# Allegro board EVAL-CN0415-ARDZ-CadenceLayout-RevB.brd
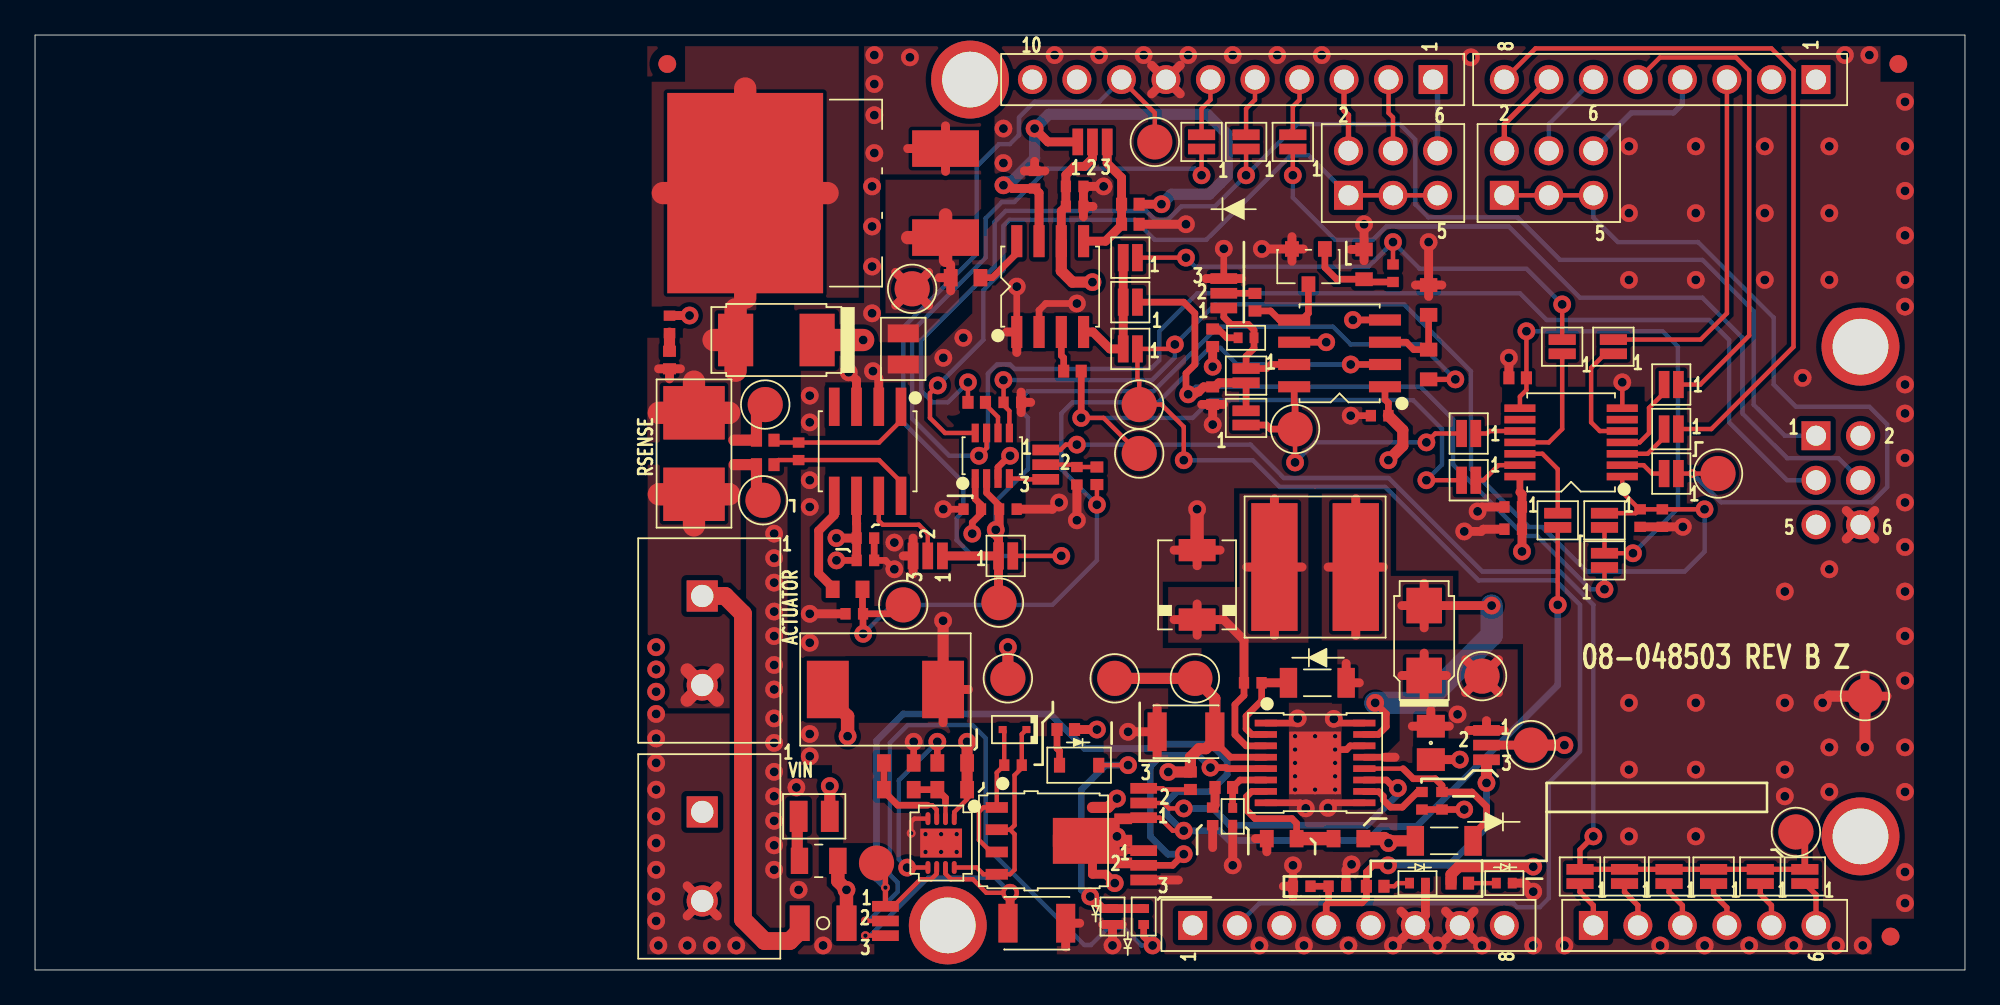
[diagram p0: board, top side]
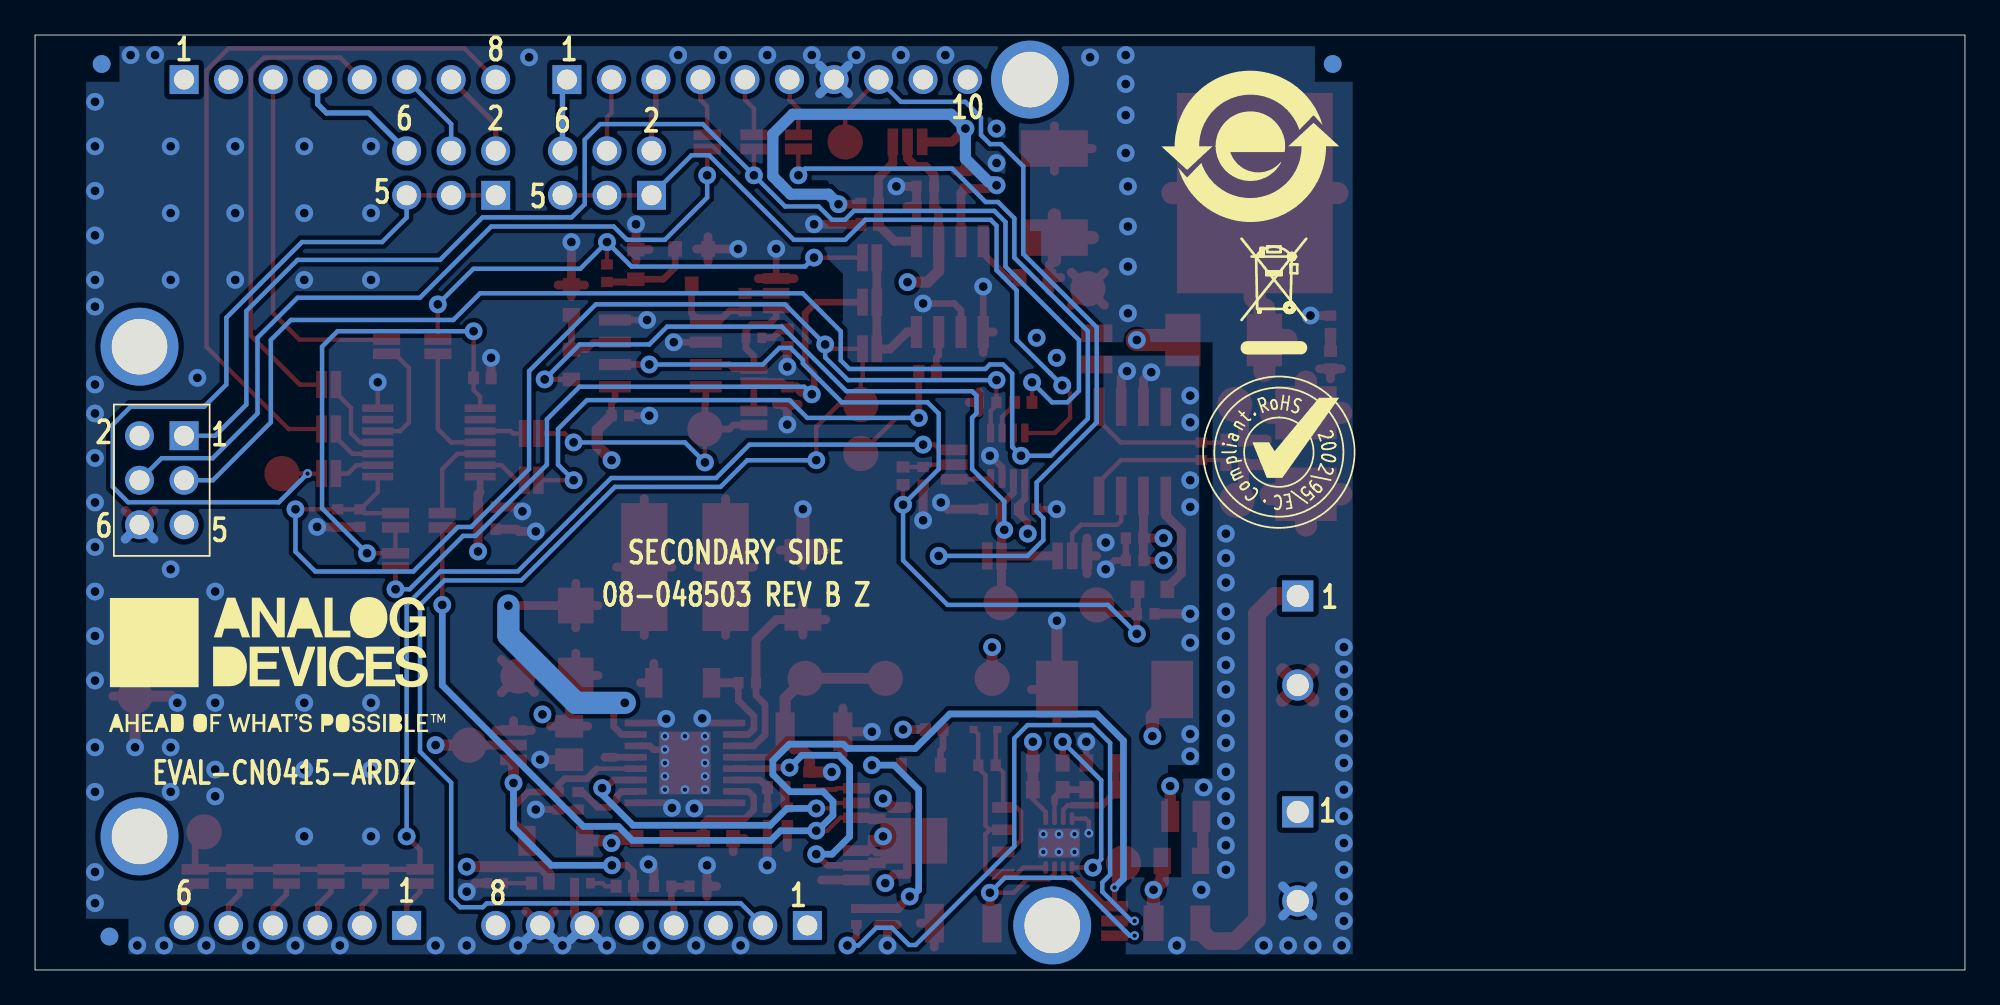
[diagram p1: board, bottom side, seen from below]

Outline 110.1 x 53.34 mm; copper layers: TOP, L2_GND, L3_PWR, BOTTOM. Coordinates in mm from the lower left corner of the outline.
Outline path: 0,53.34 0,0 110.1,0 110.1,53.34 0,53.34

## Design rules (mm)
constraint set DEFAULT: min track width 0.305

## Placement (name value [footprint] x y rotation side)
C1  0.0082uF  [C0402]  43.56 29.59 90 top
C2  4.7uF  [C0402]  59.44 28.19 270 top
C3  10uF  [C0402]  57.02 45.08 90 top
C4  4.7uF  [C0402]  53.47 26.29 180 top
C5  0.1UF  [C0402]  59.31 43.56 0 top
C6  4.7uF  [C0402]  55.75 32.38 0 top
C7  4.7uF  [C0402]  55.5 26.29 0 top
C8  4.7uF  [C0402]  84.33 26.42 180 top
C9  0.1UF  [C0402]  84.33 25.15 0 top
C10  1000pF  [C0402]  55.79 11.68 0 top
C11  0.1UF  [C0402]  47.37 23.37 0 top
C12  4.7uF  [C1210H87]  57.15 2.67 0 top
C14  2.2uF  [C1210H87]  65.66 13.59 180 top
C15  330PF  [C0402H22]  68.33 8.76 270 top
C16  0.1UF  [C0402]  69.47 16.38 180 top
C17  1000pF  [C0402]  67.18 8.76 270 top
C18  0.01UF  [C0402]  79.12 9.65 270 top
C19  0.1UF  [C0402]  80.26 9.65 270 top
C20  0.1UF  [C0402]  74.3 4.78 0 top
C21  10uF  [C0402]  72.26 4.78 180 top
C22  22UF  [C0805H60]  79.63 12.95 270 top
C23  0.1UF  [C0402]  76.71 31.62 180 top
C24  1000pF  [C0402]  36.2 36.83 90 top
C25  0.1UF  [C0402]  77.47 39.75 90 top
C26  4.7uF  [C0402]  59.31 44.7 0 top
C27  4.7uF  [C0402]  91.57 25.78 270 top
C28  0.1UF  [C0402]  92.84 25.78 90 top
C29  4.7uF  [C0402]  47.37 24.64 0 top
C30  4.7uF  [C0402]  46.74 20.32 180 top
D1  SMC3K60CAHM3/9A  [DO214AB_A]  48.51 16 0 top
D2  ACGRBT303-HF  [D2114]  42.29 35.94 180 top
D3  1SS355VMTE-17  [SOD323-4]  59.56 11.68 180 top
D4  BZX585-C15  [SOD523]  55.88 13.72 180 top
D5  B160B-13-F  [DIO214AA]  66.29 21.97 90 top
D6  FDLL914B  [SOD80C]  73.15 16.38 0 top
D7  B220A-13-F  [SMA]  79.25 18.8 90 top
D8  FDLL914B  [SOD80C]  80.39 7.37 180 top
DS1  SML-P11MTT86  [LED0402]  61.47 3.05 90 top
DS2  SML-P11VTT86  [LED0402]  63.25 3.05 90 top
DS3  SML-P11MTT86  [LED0402]  78.87 4.95 180 top
DS4  SML-P11MTT86  [LED0402]  83.82 4.95 180 top
DS5  SML-P11VTT86  [LED0402]  69.09 36.07 0 top
E1  180OHM AT 100MEGHZ  [L0805H35]  49.53 35.43 270 top
E2  180OHM AT 100MEGHZ  [L0805H35]  44.45 8.76 0 top
F1  3A  [F1206]  44.96 2.67 0 top
F2  0.5A  [F0805]  44.7 6.22 180 top
JP1  3PIN_SOLDER_JUMPER  [JPRSLD03]  50.93 23.62 180 top
JP2  3PIN_SOLDER_JUMPER  [JPRSLD03]  57.66 28.83 270 top
JP3  3PIN_SOLDER_JUMPER  [JPRSLD03]  82.8 12.83 270 top
JP4  3PIN_SOLDER_JUMPER  [JPRSLD03]  60.33 47.24 0 top
JP5  3PIN_SOLDER_JUMPER  [JPRSLD03]  63.25 5.97 270 top
JP6  3PIN_SOLDER_JUMPER  [JPRSLD03]  48.51 2.79 270 top
JP7  3PIN_SOLDER_JUMPER  [JPRSLD03]  63.25 9.52 90 top
JP8  3PIN_SOLDER_JUMPER  [JPRSLD03]  67.82 38.61 90 top
L1  100UH  [LSMSQ264H118_A]  73.03 22.99 180 top
NOREF  -  []  -45.72 -66.04 0 top
NOREF#2  -  []  135.89 92.84 0 top
NOREF#3  -  []  107.95 0.13 90 top
NOREF#4  -  [unnamed#2]  53.34 50.8 0 top
NOREF#5  -  []  -45.72 -66.04 0 top
NOREF#6  -  [unnamed#2]  52.07 2.54 0 top
NOREF#7  -  []  107.95 53.47 180 top
NOREF#8  -  []  34.16 53.47 0 top
NOREF#9  -  []  -45.72 -66.04 0 top
NOREF#10  -  []  34.16 0.13 0 top
NOREF#11  -  []  10.48 322.05 0 top
NOREF#12  -  []  70.87 62.36 0 top
NOREF#13  -  [unnamed#2]  104.14 7.62 0 top
NOREF#14  -  [unnamed#2]  106.3 51.69 0 top
NOREF#15  -  []  34.16 53.47 0 top
NOREF#16  -  [unnamed#2]  36.07 51.69 0 top
NOREF#17  -  [unnamed#2]  104.14 35.56 0 top
NOREF#18  -  []  107.95 0.13 90 top
NOREF#19  -  []  34.24 18.41 0 top
NOREF#20  -  []  34.16 7.13 0 top
NOREF#21  -  []  52.07 2.54 0 top
NOREF#22  -  []  34.16 0.13 0 top
NOREF#23  -  []  34.16 53.47 270 top
NOREF#24  -  []  107.95 0.13 0 top
NOREF#25  -  []  34.16 0.13 0 top
NOREF#26  -  []  52.07 2.54 0 top
NOREF#27  -  []  130.81 30.48 0 top
NOREF#28  -  [unnamed#2]  105.85 1.9 0 top
NOREF#29  -  []  -1.91 238.76 0 top
NOREF#30  -  []  39.14 29.54 180 bottom
NOREF#31  -  [unnamed#2]  36.07 51.69 180 bottom
NOREF#32  -  [unnamed#2]  105.85 1.9 180 bottom
NOREF#33  -  []  39.62 35.18 180 bottom
NOREF#34  -  []  40.77 46.99 180 bottom
NOREF#35  -  [unnamed#2]  106.3 51.69 180 bottom
NOREF#36  -  []  96.27 17.4 180 bottom
P1  OSTTC022162  [CNHDR1X2H406]  38.06 9.02 270 top
P2  TSW-103-08-G-D  [CNSAMTEC2X3H330LD36]  74.93 44.2 0 top
P3  SSQ-103-03-T-D  [CNSAMTECSSQ-103-XX-X-D]  101.6 30.48 270 bottom
P4  SSQ-106-03-T-S  [CNSAMTECSSQ-106-XX-X-S]  88.9 2.54 0 top
P5  SSQ-108-03-T-S  [CNSAMTECSSQ-108-XX-X-S]  66.04 2.54 0 top
P6  SSQ-110-03-T-S  [CNSAMTECSSQ-110-XX-X-S]  79.76 50.8 180 top
P7  SSQ-108-03-T-S  [CNSAMTECSSQ-108-XX-X-S]  101.6 50.8 180 top
P8  OSTTC022162  [CNHDR1X2H406]  38.06 21.34 270 top
P9  -  [JPSLD02]  55.37 23.62 0 top
P10  -  [JPSLD02]  88.14 5.33 90 top
P11  -  [JPSLD02]  90.68 5.33 90 top
P12  -  [JPSLD02]  93.22 5.33 90 top
P13  -  [JPSLD02]  95.76 5.33 90 top
P14  -  [JPSLD02]  98.43 5.33 90 top
P15  -  [JPSLD02]  100.97 5.33 90 top
P16  -  [JPSLD02]  71.75 47.24 90 top
P17  -  [JPSLD02]  69.09 47.24 90 top
P18  -  [JPSLD02]  66.55 47.24 90 top
P19  -  [JPSLD02]  81.79 27.94 180 top
P20  -  [JPSLD02]  86.87 25.65 270 top
P21  -  [JPSLD02]  69.09 33.91 270 top
P22  -  [JPSLD02]  69.09 31.5 90 top
P23  -  [JPSLD02]  87.12 35.56 90 top
P24  -  [JPSLD02]  81.79 30.61 180 top
P25  -  [JPSLD02]  93.34 28.32 180 top
P26  -  [JPSLD02]  62.48 35.43 180 top
P27  -  [JPSLD02]  62.48 40.64 180 top
P28  -  [JPSLD02]  62.48 38.1 180 top
P29  -  [JPSLD02]  93.34 30.86 180 top
P30  -  [JPSLD02]  93.34 33.4 180 top
P31  -  [JPSLD02]  90.04 35.56 270 top
P32  -  [JPSLD02]  89.53 23.37 90 top
P34  TSW-103-08-G-D  [CNSAMTEC2X3H330LD36]  83.82 44.2 0 top
P36  -  [JPSLD02]  89.53 25.65 270 top
Q1  CSD19535KTTT  [D2PAK]  44.96 44.32 90 top
Q2  SI7942DP-T1-E3  [POWERPAKSO8_DUAL]  57.53 7.37 270 top
Q3  2N7002LT1G  [SOT23-M3]  72.64 40.13 180 top
R1  0.1  [R2512-2]  37.59 29.46 90 top
R2  10  [R0402]  41.66 28.83 0 top
R3  10  [R0402]  41.66 30.23 0 top
R4  2.2  [R0603]  53.09 39.5 0 top
R5  51  [R0402]  60.58 28.19 90 top
R6  1K  [R0402]  84.58 33.78 180 top
R7  10  [R0402]  59.18 34.16 0 top
R8  10K  [R0603]  79.5 38.23 90 top
R9  2K  [R0603]  79.5 34.54 270 top
R10  84.5K  [R0402]  62.48 42.54 0 top
R11  330K  [R0402]  62.48 43.69 0 top
R12  33  [R0402]  53.72 32.38 180 top
R13  5.1K  [R0402]  58.8 13.72 180 top
R14  1MEG  [R0603]  52.32 10.29 180 top
R15  280K  [R0603]  49.28 10.29 180 top
R16  27K  [R0603]  49.28 11.81 0 top
R17  510K  [R0603]  52.32 11.81 0 top
R18  5.1K  [R0402]  76.45 4.78 0 top
R19  68K  [R0402]  67.82 10.41 180 top
R20  97.6K  [R0603]  71.12 7.49 180 top
R21  300K  [R0603]  74.93 7.49 0 top
R22  100K  [R0402]  65.91 10.79 90 top
R23  5.1K  [R0402]  81.28 4.95 0 top
R24  10K  [R0603]  75.82 40.26 90 top
R25  1K  [R0402]  67.18 32.77 270 top
R26  5.1K  [R0402]  67.18 36.07 90 top
R27  4.99K  [R0402]  69.6 38.1 270 top
R28  100  [R0402]  36.2 34.8 90 top
R29  0  [R0603]  46.36 21.72 0 top
SECONDARY SIDE  -  []  129.16 39.5 270 top
TP1  SMOX/060/B1/R2K GOLD  [CNOXLEYSMOX_060_B1]  49.53 20.83 0 top
TP2  SMOX/060/B1/R2K GOLD  [CNOXLEYSMOX_060_B1]  50.04 38.86 270 top
TP3  SMOX/060/B1/R2K GOLD  [CNOXLEYSMOX_060_B1]  62.99 29.46 180 top
TP4  SMOX/060/B1/R2K GOLD  [CNOXLEYSMOX_060_B1]  41.53 26.8 0 top
TP5  SMOX/060/B1/R2K GOLD  [CNOXLEYSMOX_060_B1]  41.66 32.26 0 top
TP6  SMOX/060/B1/R2K GOLD  [CNOXLEYSMOX_060_B1]  54.99 20.95 90 top
TP7  SMOX/060/B1/R2K GOLD  [CNOXLEYSMOX_060_B1]  61.59 16.64 90 top
TP8  SMOX/060/B1/R2K GOLD  [CNOXLEYSMOX_060_B1]  85.34 12.83 90 top
TP9  SMOX/060/B1/R2K GOLD  [CNOXLEYSMOX_060_B1]  82.55 16.76 0 top
TP10  SMOX/060/B1/R2K GOLD  [CNOXLEYSMOX_060_B1]  55.5 16.64 90 top
TP11  SMOX/060/B1/R2K GOLD  [CNOXLEYSMOX_060_B1]  104.39 15.62 180 top
TP12  SMOX/060/B1/R2K GOLD  [CNOXLEYSMOX_060_B1]  62.99 32.26 180 top
TP13  SMOX/060/B1/R2K GOLD  [CNOXLEYSMOX_060_B1]  66.17 16.64 180 top
TP14  SMOX/060/B1/R2K GOLD  [CNOXLEYSMOX_060_B1]  100.46 7.87 0 top
TP15  SMOX/060/B1/R2K GOLD  [CNOXLEYSMOX_060_B1]  96.01 28.32 270 top
TP16  SMOX/060/B1/R2K GOLD  [CNOXLEYSMOX_060_B1]  63.88 47.24 90 top
TP17  SMOX/060/B1/R2K GOLD  [CNOXLEYSMOX_060_B1]  71.88 30.86 0 top
TP18  SMOX/060/B1/R2K GOLD  [CNOXLEYSMOX_060_B1]  48.01 6.1 180 top
U1  AD8210WYRZ  [SO8]  47.5 29.59 180 top
U2  LTC4441ES8-1#PBF  [SO8NB-5]  57.91 38.99 0 top
U3  LTC2312HTS8-14#TRMPBF  [TSOT-8]  54.61 29.34 0 top
U4  ADG3304BRUZ  [TSSOP14]  87.63 30.1 90 top
U5  LTC4367CDD-1#PBF  [DFN8_3X3_PAD2_38X1_65]  51.69 7.24 180 top
U6  LT3433IFE#TRPBF  [TSSOP16_PAD3_58X2_94]  73.03 11.81 270 top
U7  LT1671IS8#PBF  [SO8NB-5]  74.42 35.18 90 top

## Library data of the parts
C1 = CAP: User Part Number: UPN; Tolerance: 10; alternate symbols: (); part number: CAP_SM-0.0082UF,16V,10,E012592,C0402; tolerance: 10
C2 C30 = CAP: User Part Number: UPN; Tolerance: 20; alternate symbols: (); part number: CAP_SM-4.7UF,6.3V,20,E014207,C0402; tolerance: 20
C3 C21 = CAP: User Part Number: UPN; Tolerance: 20; alternate symbols: (); part number: CAP_SM-10UF,10V,20,E020928,C0402; tolerance: 20
C4 C6-C8 C26 C27 C29 = CAP: User Part Number: UPN; Tolerance: 10; alternate symbols: (); part number: CAP_SM-4.7UF,6.3V,10,E020089,C0402; tolerance: 10
C5 C9 C11 C16 C19 C20 C23 C25 C28 = CAP: User Part Number: UPN; Tolerance: 10; alternate symbols: (); part number: CAP_SM-0.1UF,16V,10,E027519,C0402; tolerance: 10
C10 C17 C24 = CAP: User Part Number: UPN; Tolerance: 5; alternate symbols: (C0402L_ALT); part number: CAP_SM-1000PF,50V,5,E012419,C0402; tolerance: 5
C12 = CAP: Tolerance: 10; User Part Number: UPN; alternate symbols: (); part number: CAP_SM-4.7UF,100V,10,E023932,C1210H87; tolerance: 10
C14 = CAP: Tolerance: 10; User Part Number: UPN; alternate symbols: (); part number: CAP_SM-2.2UF,100V,10,E015185,C1210H87; tolerance: 10
C15 = CAP: Tolerance: 10; User Part Number: UPN; alternate symbols: (); part number: CAP_SM-330PF,50V,10,E033857,C0402H22; tolerance: 10
C18 = CAP: User Part Number: UPN; Tolerance: 10; alternate symbols: (); part number: CAP_SM-0.01UF,25V,10,E007203,C0402; tolerance: 10
C22 = CAP: Tolerance: 20; User Part Number: UPN; alternate symbols: (); part number: CAP_SM-22UF,25V,20,E028881,C0805H60; tolerance: 20
D1 = DIOZNR_V2: User Part Number: UPN; Tolerance: N/A; alternate symbols: (); part number: DIOZNR_V2_SM-SMC3K60CAHM3/9A,60V,N/A,E030815,DO214AB_A; tolerance: N/A
D2 = DIO: User Part Number: UPN; Tolerance: N/A; alternate symbols: (); part number: DIO_SM-ACGRBT303-HF,600V,N/A,E031289,D2114; tolerance: N/A
D3 = DIO: Tolerance: N/A; User Part Number: UPN; alternate symbols: (); part number: DIO_SM-1SS355VMTE-17,80V,N/A,E027000,SOD323-4; tolerance: N/A
D4 = DIOZNR: Tolerance: 5; User Part Number: UPN; alternate symbols: (); part number: DIOZNR_SM-BZX585-C15,15V,5,E025919,SOD523; tolerance: 5
D5 = DIOSCHOTTKY: User Part Number: UPN; Tolerance: N/A; alternate symbols: (); part number: DIOSCHOTTKY_SM-B160B-13-F,60V,N/A,E006709,DIO214AA; tolerance: N/A
D6 D8 = DIO: Tolerance: N/A; User Part Number: UPN; alternate symbols: (); part number: DIO_SM-FDLL914B,100V,N/A,E019774,SOD80C; tolerance: N/A
D7 = DIOSCHOTTKY: User Part Number: UPN; Tolerance: N/A; alternate symbols: (); part number: DIOSCHOTTKY_SM-B220A-13-F,20V,N/A,E007403,SMA; tolerance: N/A
DS1 DS3 DS4 = DIOLED: User Part Number: UPN; Tolerance: N/A; alternate symbols: (); part number: DIOLED_SM-SML-P11MTT86,N/A,N/A,E014445,LED0402; tolerance: N/A
DS2 DS5 = DIOLED: User Part Number: UPN; Tolerance: N/A; alternate symbols: (); part number: DIOLED_SM-SML-P11VTT86,N/A,N/A,E019415,LED0402; tolerance: N/A
E1 E2 = FERRITE: Tolerance: 25; User Part Number: UPN; alternate symbols: (); part number: FERRITE_SM-180OHM AT 100MEGHZ,25,E017991,L0805H35; tolerance: 25
F1 = FSFUSE: Tolerance: N/A; User Part Number: UPN; alternate symbols: (); part number: FSFUSE_SM-3A,32V,E005229,F1206; tolerance: N/A
F2 = FSFUSE: User Part Number: UPN; Tolerance: N/A; alternate symbols: (); part number: FSFUSE_SM-0.5A,6V,E016128,F0805; tolerance: N/A
JP1-JP8 = NC3P_JMPR: Tolerance: N/A; User Part Number: UPN; alternate symbols: (); part number: NC3P_JMPR_SM-3PIN_SOLDER_JUMPER,E005606,JPRSLD03; tolerance: N/A
L1 = IND: Tolerance: 30; User Part Number: UPN; alternate symbols: (); part number: IND_SM-100UH,30,E031309,LSMSQ264H118_A; tolerance: 30
P1 P8 = CN2P: User Part Number: UPN; Tolerance: N/A; alternate symbols: (); part number: CN2P_TH-OSTTC022162,E016936,CNHDR1X2H406; tolerance: N/A
P2 P34 = CN6P_ODD_EVEN: Tolerance: N/A; User Part Number: UPN; alternate symbols: (); part number: CN6P_ODD_EVEN_TH-TSW-103-08-G-D,E006383,CNSAMTEC2X3H330LD36; tolerance: N/A
P3 = CN6P: User Part Number: UPN; Tolerance: N/A; alternate symbols: (); part number: CN6P_TH-SSQ-103-03-T-D,E027152,CNSAMTECSSQ-103-XX-X-D; tolerance: N/A
P4 = CN6P: User Part Number: UPN; Tolerance: N/A; alternate symbols: (); part number: CN6P_TH-SSQ-106-03-T-S,E027150,CNSAMTECSSQ-106-XX-X-S; tolerance: N/A
P5 P7 = CN8P_A: User Part Number: UPN; Tolerance: N/A; alternate symbols: (); part number: CN8P_A_TH-SSQ-108-03-T-S,E027149,CNSAMTECSSQ-108-XX-X-S; tolerance: N/A
P6 = CN10P: User Part Number: UPN; Tolerance: N/A; alternate symbols: (); part number: CN10P_TH-SSQ-110-03-T-S,E027151,CNSAMTECSSQ-110-XX-X-S; tolerance: N/A
P9-P32 P36 = NC2P: User Part Number: UPN; Tolerance: N/A; alternate symbols: (); part number: NC2P_SM-JPSLD02,E006230,JPSLD02; tolerance: N/A
Q1 = TRANNMOSFET_V21: Tolerance: N/A; User Part Number: UPN; alternate symbols: (); part number: TRANNMOSFET_V21_SM-CSD19535KTTT,E031287,D2PAK; tolerance: N/A
Q2 = TRANNMOSFET_DUAL: Tolerance: N/A; User Part Number: UPN; alternate symbols: (); part number: TRANNMOSFET_DUAL_SM-SI7942DP-T1-E3,E030882,POWERPAKSO8_DUAL; tolerance: N/A
Q3 = TRAN2N7002: User Part Number: UPN; Tolerance: N/A; alternate symbols: (); part number: TRAN2N7002_SM-2N7002LT1G,E005348,SOT23-M3; tolerance: N/A
R1 = RES: User Part Number: UPN; Tolerance: 1; alternate symbols: (); part number: RES_SM-0.1,E013380,1W,1,R2512-2; tolerance: 1
R2 R3 R7 = RES: User Part Number: UPN; Tolerance: 1; alternate symbols: (R0402L,R0402L_ALT); part number: RES_SM-10,E003768,1/16W,1,R0402; tolerance: 1
R4 = RES: User Part Number: UPN; Tolerance: 1; alternate symbols: (R0603L); part number: RES_SM-2.2,E017481,1/10W,1,R0603; tolerance: 1
R5 = RES: User Part Number: UPN; Tolerance: 5; alternate symbols: (R0402L); part number: RES_SM-51,E003442,1/16W,5,R0402; tolerance: 5
R6 R25 = RES: User Part Number: UPN; Tolerance: 5; alternate symbols: (R0402L); part number: RES_SM-1K,E020936,1/16W,5,R0402; tolerance: 5
R8 R24 = RES: User Part Number: UPN; Tolerance: 1; alternate symbols: (); part number: RES_SM-10K,E031925,1/8W,1,R0603; tolerance: 1
R9 = RES: User Part Number: UPN; Tolerance: 1; alternate symbols: (R0603L); part number: RES_SM-2K,E003711,1/10W,1,R0603; tolerance: 1
R10 = RES: User Part Number: UPN; Tolerance: 1; alternate symbols: (R0402L); part number: RES_SM-84.5K,E019618,1/16W,1,R0402; tolerance: 1
R11 = RES: User Part Number: UPN; Tolerance: 1; alternate symbols: (R0402L); part number: RES_SM-330K,E025663,1/16W,1,R0402; tolerance: 1
R12 = RES: User Part Number: UPN; Tolerance: 1; alternate symbols: (R0402L); part number: RES_SM-33,E020519,1/10W,1,R0402; tolerance: 1
R13 R18 R23 R26 = RES: User Part Number: UPN; Tolerance: 1; alternate symbols: (R0402L); part number: RES_SM-5.1K,E019615,1/16W,1,R0402; tolerance: 1
R14 = RES: User Part Number: UPN; Tolerance: 1; alternate symbols: (); part number: RES_SM-1MEG,E030873,1/10W,1,R0603; tolerance: 1
R15 = RES: User Part Number: UPN; Tolerance: 1; alternate symbols: (); part number: RES_SM-280K,E030872,1/10W,1,R0603; tolerance: 1
R16 = RES: User Part Number: UPN; Tolerance: 1; alternate symbols: (R0603L); part number: RES_SM-27K,E004226,1/16W,1,R0603; tolerance: 1
R17 = RES: User Part Number: UPN; Tolerance: 1; alternate symbols: (R0603L); part number: RES_SM-510K,E026533,1/10W,1,R0603; tolerance: 1
R19 = RES: User Part Number: UPN; Tolerance: 5; alternate symbols: (R0402L); part number: RES_SM-68K,E021885,1/16W,5,R0402; tolerance: 5
R20 = RES: User Part Number: UPN; Tolerance: 1; alternate symbols: (); part number: RES_SM-97.6K,E031992,1/10W,1,R0603; tolerance: 1
R21 = RES: User Part Number: UPN; Tolerance: 0.1; alternate symbols: (R0603L); part number: RES_SM-300K,E024299,1/10W,0.1,R0603; tolerance: 0.1
R22 = RES: User Part Number: UPN; Tolerance: 1; alternate symbols: (R0402L,R0402L_ALT); part number: RES_SM-100K,E003796,1/16W,1,R0402; tolerance: 1
R27 = RES: User Part Number: UPN; Tolerance: 1; alternate symbols: (R0402L); part number: RES_SM-4.99K,E006643,1/16W,1,R0402; tolerance: 1
R28 = RES: User Part Number: UPN; Tolerance: 5; alternate symbols: (R0402L); part number: RES_SM-100,E003443,1/10W,5,R0402; tolerance: 5
R29 = RES: User Part Number: UPN; Tolerance: 1; alternate symbols: (R0603L); part number: RES_SM-0,E004207,1/16W,1,R0603; tolerance: 1
TP1-TP18 = CNTP1P: Tolerance: N/A; User Part Number: UPN; alternate symbols: (); part number: CNTP1P_SM-GOLD,E023771,CNOXLEYSMOX_060_B1; tolerance: N/A
U1 = AD8210: Tolerance: N/A; User Part Number: UPN; alternate symbols: (); part number: AD8210_SM-AD8210WYRZ,E012674,SO8; tolerance: N/A
U2 = LINLTC4441: Tolerance: N/A; User Part Number: UPN; alternate symbols: (); part number: LINLTC4441_SM-LTC4441ES8-1#PBF,E030785,SO8NB-5; tolerance: N/A
U3 = LINLTC2312_14: User Part Number: UPN; Tolerance: N/A; alternate symbols: (); part number: LINLTC2312_14_SM-LTC2312HTS8-14#TRMPBF,E030784,TSOT-8; tolerance: N/A
U4 = ADG3304: Tolerance: N/A; User Part Number: UPN; alternate symbols: (); part number: ADG3304_SM-ADG3304BRUZ,E007035,TSSOP14; tolerance: N/A
U5 = LINLTC4367: User Part Number: UPN; Tolerance: N/A; alternate symbols: (); part number: LINLTC4367_SM-LTC4367CDD-1#PBF,E030775,DFN8_3X3_PAD2_38X1_65; tolerance: N/A
U6 = LINLT3433: User Part Number: UPN; Tolerance: N/A; alternate symbols: (); part number: LINLT3433_SM-LT3433IFE#TRPBF,E030777,TSSOP16_PAD3_58X2_94; tolerance: N/A
U7 = LINLT1671: Tolerance: N/A; User Part Number: UPN; alternate symbols: (); part number: LINLT1671_SM-LT1671IS8#PBF,E031612,SO8NB-5; tolerance: N/A

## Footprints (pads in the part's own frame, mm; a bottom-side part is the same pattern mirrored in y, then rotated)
C0402
  rect 0.584x0.66 smd: 1(-0.5,0) 2(0.5,0)
C0402H22
  rect 0.559x0.508 smd: 1(-0.479,0) 2(0.479,0)
C0805H60
  rect 1.295x1.6 smd: 1(-0.953,0) 2(0.953,0)
C1210H87
  rect 1.092x2.21 smd: 1(-1.646,0) 2(1.646,0)
CNHDR1X2H406
  rect 1.778x1.778 hole 1.27: 1(0,0)
  round 1.778 hole 1.27: 2(5.08,0)
CNOXLEYSMOX_060_B1
  round 2.007 smd: 1(0,0)
CNSAMTEC2X3H330LD36
  rect 1.651x1.651 hole 1.143: 1(0,0)
  round 1.651 hole 1.143: 2(0,2.54) 3(2.54,0) 4(2.54,2.54) 5(5.08,0) 6(5.08,2.54)
CNSAMTECSSQ-103-XX-X-D
  rect 1.651x1.651 hole 1.143: 1(0,0)
  round 1.651 hole 1.143: 2(0,-2.54) 3(2.54,0) 4(2.54,-2.54) 5(5.08,0) 6(5.08,-2.54)
CNSAMTECSSQ-106-XX-X-S
  rect 1.651x1.651 hole 1.143: 1(0,0)
  round 1.651 hole 1.143: 2(2.54,0) 3(5.08,0) 4(7.62,0) 5(10.16,0) 6(12.7,0)
CNSAMTECSSQ-108-XX-X-S
  rect 1.651x1.651 hole 1.143: 1(0,0)
  round 1.651 hole 1.143: 2(2.54,0) 3(5.08,0) 4(7.62,0) 5(10.16,0) 6(12.7,0) 7(15.24,0) 8(17.78,0)
CNSAMTECSSQ-110-XX-X-S
  rect 1.651x1.651 hole 1.143: 1(0,0)
  round 1.651 hole 1.143: 2(2.54,0) 3(5.08,0) 4(7.62,0) 5(10.16,0) 6(12.7,0) 7(15.24,0) 8(17.78,0) 9(20.32,0) 10(22.86,0)
D2PAK
  rect 2.083x3.81 smd: 1(-2.54,-6.985) 3(2.54,-6.985)
  rect 11.43x8.89 smd: 4(0,4.445)
D2114
  rect 2.007x2.997 smd: A(2.324,0) C(-2.324,0)
DFN8_3X3_PAD2_38X1_65
  oval 0.279x0.737 smd: 1(-0.75,-1.393) 2(-0.25,-1.393) 3(0.25,-1.393) 4(0.75,-1.393) 5(0.75,1.393) 6(0.25,1.393) 7(-0.25,1.393) 8(-0.75,1.393)
  rect 2.388x1.651 smd: PAD(0,0)
DIO214AA
  rect 1.27x2.108 smd: A(1.981,0) C(-1.981,0)
DO214AB_A
  rect 2.388x3.277 smd: 1(-3.289,0) 2(3.289,0)
F0805
  rect 0.991x1.499 smd: 1(-1.095,0) 2(1.095,0)
F1206
  rect 1.143x2.032 smd: 1(-1.333,0) 2(1.333,0)
JPRSLD03
  rect 0.61x1.524 smd: 1(-0.838,0) 2(0,0) 3(0.838,0)
JPSLD02
  rect 0.61x1.549 smd: 1(-0.406,0) 2(0.406,0)
L0805H35
  rect 1.016x1.778 smd: 1(-0.889,0) 2(0.889,0)
LED0402
  rect 0.508x0.61 smd: A(0.454,0) C(-0.454,0)
LSMSQ264H118_A
  rect 2.642x7.29 smd: 1(-2.321,0) 2(2.321,0)
POWERPAKSO8_DUAL
  rect 0.61x1.27 smd: 1(-1.905,-2.667) 2(-0.635,-2.667) 3(0.635,-2.667) 4(1.905,-2.667)
  round 0.127 smd: 5(1.905,2.794) 8(-1.905,2.794)
  custom 0.476x0.476 smd: 6(0.61,2.794) 7(-0.61,2.794)
R0402
  rect 0.635x0.737 smd: 1(-0.5,0) 2(0.5,0)
R0603
  rect 0.787x0.991 smd: 1(-0.85,0) 2(0.85,0)
R2512-2
  rect 3.048x3.505 smd: 1(-2.324,0) 2(2.324,0)
SMA
  rect 2.032x2.032 smd: A(1.994,0) C(-1.994,0)
SO8
  rect 0.61x2.184 smd: 1(-1.905,-2.54) 2(-0.635,-2.54) 3(0.635,-2.54) 4(1.905,-2.54) 5(1.905,2.54) 6(0.635,2.54) 7(-0.635,2.54) 8(-1.905,2.54)
SO8NB-5
  rect 0.635x1.829 smd: 1(-1.905,-2.591) 2(-0.635,-2.591) 3(0.635,-2.591) 4(1.905,-2.591) 5(1.905,2.591) 6(0.635,2.591) 7(-0.635,2.591) 8(-1.905,2.591)
SOD80C
  rect 0.991x1.702 smd: A(1.645,0) C(-1.645,0)
SOD323-4
  rect 0.635x0.838 smd: A(1.118,0) C(-1.118,0)
SOD523
  rect 0.457x0.406 smd: A(0.679,0) C(-0.679,0)
SOT23-M3
  rect 0.787x0.889 smd: 1(-0.94,-1.003) 2(0.94,-1.003) 3(0,1.003)
TSOT-8
  rect 0.406x1.067 smd: 1(-0.975,-1.3) 2(-0.325,-1.3) 3(0.325,-1.3) 4(0.975,-1.3) 5(0.975,1.3) 6(0.325,1.3) 7(-0.325,1.3) 8(-0.975,1.3)
TSSOP14
  rect 0.432x1.778 smd: 1(-1.95,-2.92) 2(-1.3,-2.92) 3(-0.65,-2.92) 4(0,-2.92) 5(0.65,-2.92) 6(1.3,-2.92) 7(1.95,-2.92) 8(1.95,2.92) 9(1.3,2.92) 10(0.65,2.92) 11(0,2.92) 12(-0.65,2.92) 13(-1.3,2.92) 14(-1.95,2.92)
TSSOP16_PAD3_58X2_94
  rect 0.381x1.27 smd: 1(-2.275,-2.81) 2(-1.625,-2.81) 3(-0.975,-2.81) 4(-0.325,-2.81) 5(0.325,-2.81) 6(0.975,-2.81) 7(1.625,-2.81) 8(2.275,-2.81) 9(2.275,2.81) 10(1.625,2.81) 11(0.975,2.81) 12(0.325,2.81) 13(-0.325,2.81) 14(-0.975,2.81) 15(-1.625,2.81) 16(-2.275,2.81)
  rect 3.581x2.946 smd: PAD(0,0)
unnamed#2
  round 4.445 hole 3.175 unplated: (0,0)

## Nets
+3V3_ARD: C20.1 C21.1 JP3.3 P5.4 R18.1
+5V_ARD: P5.5
AGND: C2.2(N2) C3.2(N2) C4.2(N2) C5.2(N2) C6.2(N2) C7.2(N2) C8.2(N2) C9.1 C11.2(N2) C12.2(N2) C14.2(N2) C15.2(N2) C17.2(N2) C18.2(N2) C19.2(N2) C20.2(N2) C21.2(N2) C22.2(N2) C23.2(N2) C26.2(N2) C27.2(N2) C28.1 C29.2(N2) C30.2(N2) D1.2(N2) D5.A(P) DS1.C DS3.C DS4.C E1.2(N2) JP1.3 JP5.3 JP8.3 P3.6(N6) P5.6 P5.7 P6.7 Q3.2(S) R6.2(N2) R8.2(N2) R10.2(N2) R16.2(N2) R20.2(N2) R24.2(N2) R25.2(N2) R26.1 TP11.1(N1) U1.2 U1.3 U2.1 U2.2 U3.3 U4.7 U5.4 U5.PAD U6.1 U6.8 U6.9 U6.14 U6.16 U6.PAD U7.4(V-) U7.6
PGND: C24.2(N2) E1.1 P1.2(N2) Q1.3(S)
VCC: C4.1 C11.1 C29.1 JP3.2(COM) R23.1 TP8.1(N1) U1.6(V_POS) U3.1(VDD)
VIN: D1.1 E2.2(N2) Q2.7 Q2.8 R13.1 R14.1 R17.2(N2) TP10.1(N1) U5.1
AD8210_OUTPUT: C30.1 R5.1 R29.2(N2) TP1.1(N1) U7.2
AIN_ARD: JP2.1 P10.2(N2) P11.2(N2) P12.2(N2) P13.2(N2) P14.2(N2) P15.2(N2) TP14.1(N1)
AREF_ARD: P6.8 P9.2(N2) TP16.1(N1)
FAULT_DETECT: P22.1 P24.2(N2) TP17.1(N1) U7.8
FAULT_DETECT_ARD: P7.3 P31.1
FET_DRIVER_OUTPUT: Q1.1 R4.1 TP2.1(N1)
IOREF: C6.1 C27.1 C28.2(N2) P5.2 P26.1 P36.1 TP12.1(N1) U3.5 U4.1
LOGICTRANSLATOROUTPUT: P19.2(N2) R7.2(N2) TP3.1(N1)
LT1671_QN_OUT: P21.2(N2) P22.2(N2) P28.1 P32.1 R25.1
LT3433_EN: JP7.3 R22.1
LT4367_FAULT_ARD: P7.8(N8) P29.1
LTC2312_CONV: P2.1 P2.3 P2.5 U3.8
LTC2312_VREF: C7.1 JP1.1 P9.1 R9.2(N2) TP6.1(N1) U3.2
LTC4367_FAULT: JP6.1 JP7.1 P20.2(N2) TP18.1(N1) U5.6
LTC4441_DRVCC: C3.1 JP4.1 R11.2(N2) U2.7
LTC4441_FB: JP4.3 R10.1 R11.1 U2.5
MISO_ARD: P3.1 P17.1 R12.2(N2)
MOSI_ARD: P3.4 P16.1
OC_RESET: C25.2(N2) P23.2(N2) P27.1
OC_RESET_ARD: P7.5 P30.1
PWM_SIG: P25.1 P34.1 P34.3 P34.5 TP15.1(N1)
RSENSE_N: D2.A(P) Q1.4 R1.2(N2) R3.1 R28.1 TP5.1(N1)
RSENSE_P: P8.2(N2) R1.1 R2.1 TP4.1(N1)
SCL_ARD: P6.10
SCLK_ARD: P3.3 P18.1 U3.7
SDA_ARD: P6.9(N9)
SHDN_N_LTC4367: R17.1 U5.5
SW_H_LT3433: C16.2(N2) D5.C L1.2(N2) U6.3
UNNAMED_4_AD8210_I5_INV: C1.2(N2) R3.2(N2) U1.1
UNNAMED_4_AD8210_I5_NINV: C1.1 R2.2(N2) U1.8
UNNAMED_4_AD8210_I5_OUT: R29.1 U1.5
UNNAMED_4_AD8210_I5_VREF1: JP1.2(COM) U1.7
UNNAMED_4_ADG3304_I147_A1: P25.2(N2) U4.2
UNNAMED_4_ADG3304_I147_A2: P29.2(N2) U4.3
UNNAMED_4_ADG3304_I147_A3: P30.2(N2) U4.4
UNNAMED_4_ADG3304_I147_A4: P31.2(N2) U4.5
UNNAMED_4_ADG3304_I147_EN: P32.2(N2) P36.2(N2) R6.1 U4.8
UNNAMED_4_ADG3304_I147_Y1: P19.1 U4.13
UNNAMED_4_ADG3304_I147_Y2: P20.1 U4.12
UNNAMED_4_ADG3304_I147_Y3: P23.1 U4.11
UNNAMED_4_ADG3304_I147_Y4: P24.1 U4.10(Y4)
UNNAMED_4_CAP_I113_N1: C24.1 R28.2(N2)
UNNAMED_4_CAP_I138_N1: C25.1 Q3.1 R24.1
UNNAMED_4_CAP_I190_N1: C2.1 JP2.2(COM) R5.2(N2)
UNNAMED_4_CN2P_I185_N1: D2.C F1.2(N2) F2.1 P1.1
UNNAMED_4_CN2P_I186_N1: F1.1 P8.1
UNNAMED_4_DIOLED_I105_N: DS5.C R26.2(N2)
UNNAMED_4_DIOLED_I105_P: DS5.A(P) JP8.1 P21.1 U7.7
UNNAMED_4_FERRITE_I59_N1: E2.1 F2.2(N2)
UNNAMED_4_LINLT1671_I98_: R8.1 R9.1 U7.3
UNNAMED_4_LINLT1671_I98_LATCHEN: Q3.3 R27.2(N2) U7.5
UNNAMED_4_LINLTC4441_I24_IN: R7.1 U2.3
UNNAMED_4_LINLTC4441_I24_OUT: R4.2(N2) U2.8
UNNAMED_4_LINLTC231214_I50_AIN: JP2.3 U3.4
UNNAMED_4_LINLTC231214_I50_SDO: R12.1 U3.6
UNNAMED_4_NC2P_I121_N2: P26.2(N2) P27.2(N2) P28.2(N2) U2.4
UNNAMED_4_NC3PJMPR_I135_COM: JP8.2(COM) R27.1
UNNAMED_5_CN6P_I88_N1: P4.1 P10.1
UNNAMED_5_CN6P_I88_N2: P4.2 P11.1
UNNAMED_5_CN6P_I88_N3: P4.3 P12.1
UNNAMED_5_CN6P_I88_N4: P4.4 P13.1
UNNAMED_5_CN6P_I88_N5: P4.5 P14.1
UNNAMED_5_CN6P_I88_N6: P4.6(N6) P15.1
UNNAMED_5_CN6PODDEVEN_I95_N2: P7.7 P34.2
UNNAMED_5_CN6PODDEVEN_I95_N4: P7.6 P34.4
UNNAMED_5_CN6PODDEVEN_I95_N6: P7.4 P34.6(N6)
UNNAMED_5_CN10P_I91_N1: P2.6(N6) P6.1
UNNAMED_5_CN10P_I91_N2: P2.4 P6.2
UNNAMED_5_CN10P_I91_N3: P2.2 P6.3
UNNAMED_5_CN10P_I91_N4: P6.4 P16.2(N2)
UNNAMED_5_CN10P_I91_N5: P6.5 P17.2(N2)
UNNAMED_5_CN10P_I91_N6: P6.6 P18.2(N2)
UNNAMED_6_CAP_I20_N1: C19.1 D8.C U6.12
UNNAMED_6_CAP_I25_N1: C16.1 D6.C U6.2
UNNAMED_6_CAP_I27_N1: C18.1 U6.10
UNNAMED_6_CAP_I32_N1: C17.1 R19.2(N2)
UNNAMED_6_CAP_I34_N1: C15.1 R19.1 U6.6
UNNAMED_6_DIO_I54_N: D3.C DS1.A(P) DS2.A(P)
UNNAMED_6_DIO_I54_P: D3.A(P) R13.2(N2)
UNNAMED_6_DIOLED_I52_N: DS2.C JP6.2(COM)
UNNAMED_6_DIOLED_I60_P: DS3.A(P) R18.2(N2)
UNNAMED_6_DIOLED_I63_P: DS4.A(P) R23.2(N2)
UNNAMED_6_DIOSCHOTTKY_I22_P: D7.A(P) L1.1 U6.15
UNNAMED_6_DIOZNR_I46_N: C10.2(N2) D4.C Q2.2 Q2.4 U5.8
UNNAMED_6_DIOZNR_I46_P: C10.1 D4.A(P) Q2.1 Q2.3(S)
UNNAMED_6_LINLT3433_I2_BURSTEN: JP5.2(COM) U6.5
UNNAMED_6_LINLT3433_I2_SHDNN: JP7.2(COM) U6.11
UNNAMED_6_LINLT3433_I2_VFB: R20.1 R21.1 U6.7
UNNAMED_6_LINLTC4367_I1_OV: R15.2(N2) R16.1 U5.3
UNNAMED_6_LINLTC4367_I1_UV: R14.2(N2) R15.1 U5.2
VOUT_LT3433: C8.1 C9.2(N2) C22.1 C23.1 D6.A(P) D7.C D8.A(P) JP3.1 R21.2(N2) TP9.1(N1) U4.14 U6.13(VOUT) U7.1
VOUT_LTC4367: C5.1 C12.1 C14.1 C26.1 JP4.2(COM) JP5.1 JP6.3 Q2.5 Q2.6 R22.2(N2) TP7.1(N1) TP13.1(N1) U2.6(VIN) U5.7(VOUT) U6.4

Pads without a net: P3 2 5; P5 1 3 8; P7 1 2; U1 4; U4 6 9

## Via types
v1: diameter 1.016, hole 0.508, TOP to BOTTOM, 235 vias
v2: diameter 0.508, hole 0.254, TOP to BOTTOM, 23 vias

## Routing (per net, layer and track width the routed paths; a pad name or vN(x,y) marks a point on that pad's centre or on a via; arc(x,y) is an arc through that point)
+3V3_ARD: length 18.9
  TOP w0.381: 73.79,3.83 73.66,3.7 P5.4 ; 73.79,3.83 C20.1 C21.1 ; 73.79,3.83 75.7,3.83 75.95,4.08 R18.1 75.95,5.59 76.33,5.97 v1(77.19,5.97)
  TOP w0.635: JP3.3 v1(82.8,10.67)
  BOTTOM w0.381: v1(82.8,10.67) 82.8,8.13 80.64,5.97 v1(77.19,5.97)
AGND: length 177
  TOP w0.254: U4.7 v1(90.55,33.53) ; U5.4 50.16,8.63 49.98,8.45 v2(49.98,7.8)
  TOP w0.381: U6.8 72.18,9.54 v1(72.49,9.22) ; U3.3 54.94,28.68 55.59,29.34 v1(55.63,29.34) ; U6.9 74.05,9.54 v1(73.76,9.25) ; C23.2 75.18,31.62 ; v1(74.09,14.33) 74.33,14.09 U6.16 ; U2.1 v1(56.01,38.99) ; JP8.3 v1(67.82,41.15) ; v2(74.17,12.57) 74.82,12.57 75.03,12.79 U6.14 ; U7.6 v1(73.66,35.81) ; v1(72.03,14.35) 71.77,14.09 U6.1 ; C18.2 C19.2 v1(81.53,9.15) ; v1(59.44,38.02) 57.66,38.02 57.28,37.64 U2.2 ; v1(51.82,26.29) C4.2 ; C29.2 C11.2 48.51,23.37 v1(49.02,22.86) ; U7.4 v1(75.18,37.08) ; R16.2 v1(50.13,13.02)
  TOP w0.508: v1(85.47,4.47) 84.99,4.95 DS4.C ; 59.81,42.98 C5.2 ; C5.2 60.36,43.56 ; C5.2 C26.2 v1(60.96,44.7) ; C6.2 56.8,32.38 ; C6.2 56.25,31.8 ; C6.2 56.25,32.97 ; C14.2 64.01,14.95 ; C14.2 v1(62.36,13.59) ; C14.2 64.01,12.23 ; R10.2 v1(65.66,42.54) ; 104.39,16.88 TP11.1 105.65,15.62 ; C3.2 57.02,46.13 ; C3.2 57.61,45.59 ; C3.2 56.44,45.59 ; 70.27,6.74 R20.2 69.62,7.49 ; 77.93,3.35 P5.6 ; P5.6 77.93,1.73 ; P5.6 79.32,3.12 DS3.C ; P5.6 79.55,1.73 ; P3.6 104.95,24.59 ; P3.6 103.33,26.21 ; P3.6 103.33,24.59 ; P3.6 104.95,26.21 ; R25.2 67.81,32.27 ; R25.2 66.56,32.27 ; R25.2 v1(67.18,31.11) ; 75.07,41.11 R24.2 ; R24.2 75.82,40.46 ; R24.2 v1(75.82,42.54) 75.82,42.61 ; 66.29,23.06 D5.A ; D5.A 64.99,23.95 ; D5.A 67.6,23.95 ; 63.7,49.99 P6.7 ; P6.7 65.33,49.99 ; P6.7 65.33,51.61 ; P6.7 63.7,51.61 ; v1(81.53,25.02) 82.5,25.02 82.63,25.15 C9.1 ; C27.2 C28.1 v1(94.01,25.28) ; 71.7,40.44 Q3.2 ; Q3.2 72.35,41.14 ; Q3.2 v1(69.99,41.14) ; Q3.2 71.7,41.83 ; 59.6,2.67 C12.2 58.8,1.31 ; 56.01,35.23 U2.1 55.43,36.4 ; C30.2 v1(44.2,20.32) ; P5.7 82.09,1.73 ; P5.7 82.09,3.35 ; P5.7 80.47,3.35 ; P5.7 80.47,1.73 ; DS1.C 62.03,2.59 ; DS1.C v1(61.47,1.4) ; DS1.C 60.91,2.59 ; C2.2 v1(59.44,25.65) ; JP5.3 65.23,5.13 ; 51.8,14.11 D1.2 53.25,16 ; v1(47.8,34.16) 47.8,34.1 48.13,33.77 U1.2 ; v1(75.11,6.02) 74.8,5.71 C20.2 ; C8.2 82.55,26.42 v1(82.3,26.16) ; 71.76,4.19 C21.2 ; C21.2 71.22,4.78 ; C21.2 71.76,5.36 ; R8.2 80.25,39.08 ; R8.2 78.75,39.08 ; R8.2 v1(79.5,41.53) ; R8.2 79.5,38.43 ; C22.2 v1(81.28,12) ; C15.2 v1(68.33,5.97) ; 50.09,22.61 JP1.3 ; JP1.3 49.53,23.62 ; JP1.3 50.09,24.64 ; 68.83,39.45 JP8.3 66.8,39.45 ; v1(46.42,34.1) 46.86,33.66 U1.3 ; v1(67.18,34.42) R26.1 ; v1(58.42,26.67) 58.04,26.29 C7.2 ; C17.2 67.18,6.98 ; R6.2 v1(84.08,34.92)
  TOP w0.635: v1(101.98,15.24) 102.36,15.62 TP11.1 v1(104.39,12.7) ; D1.2 v1(51.8,19.93)
  TOP w0.762: D5.A v1(66.29,26.29)
  L2_GND w0.508: P3.6 104.95,26.21 ; P3.6 103.33,24.59 ; P3.6 104.95,24.59 ; P3.6 103.33,26.21 ; 80.47,1.73 P5.7 ; P5.7 82.09,3.35 ; P5.7 80.47,3.35 ; P5.7 82.09,1.73 ; P5.6 79.55,3.35 ; P5.6 77.93,1.73 ; P5.6 79.55,1.73 ; P5.6 77.93,3.35 ; 63.7,49.99 P6.7 ; P6.7 63.7,51.61 ; P6.7 65.33,49.99 ; P6.7 65.33,51.61
  BOTTOM w0.508: 104.95,24.59 P3.6 103.33,24.59 ; 82.09,1.73 P5.7 80.47,1.73 ; 79.55,1.73 P5.6 77.93,1.73 ; P6.7 65.33,49.99 ; P6.7 63.7,51.61 ; P6.7 63.7,49.99 ; P6.7 65.33,51.61
  vias: v1(44.2,32.77) v1(44.2,31.24) v1(44.2,27.94) v1(44.2,26.42) v1(44.2,18.67) v1(44.2,13.46) v1(44.2,12.19) v1(49.02,24.38) v1(51.82,34.92) v1(52.96,36.07) v1(55.24,48.01) v1(55.24,46.04) v1(58.17,52.2) v1(60.71,52.2) v1(63.25,52.2) v1(65.79,52.2) v1(68.33,52.2) v1(69.85,1.4) v1(70.87,52.2) v1(71.76,5.97) v1(72.39,1.4) v1(73.41,52.2) v1(74.93,1.4) v1(75.06,31.62) v1(77.47,1.4) v1(80.01,1.4) v1(81.91,52.07) v1(82.55,1.4) v1(85.47,1.4) v1(87.25,1.4) v1(90.93,46.99) v1(90.93,43.18) v1(90.93,39.37) v1(90.93,15.24) v1(90.93,11.43) v1(90.93,7.62) v1(92.71,1.4) v1(94.74,46.99) v1(94.74,43.18) v1(94.74,39.37) v1(94.74,15.24) v1(94.74,11.43) v1(94.74,7.62) v1(95.25,1.4) v1(97.79,1.4) v1(98.68,46.99) v1(98.68,43.18) v1(98.68,39.37) v1(99.82,21.59) v1(99.82,15.24) v1(99.82,11.43) v1(99.82,9.91) v1(100.33,1.4) v1(100.84,33.78) v1(102.36,46.99) v1(102.36,43.18) v1(102.36,39.37) v1(102.36,22.86) v1(102.36,12.7) v1(102.36,10.16) v1(102.74,1.4) v1(103.25,52.2) v1(104.27,1.4) v1(104.65,52.2) v1(106.68,49.53) v1(106.68,46.99) v1(106.68,44.45) v1(106.68,41.91) v1(106.68,39.37) v1(106.68,37.85) v1(106.68,33.4) v1(106.68,31.75) v1(106.68,29.21) v1(106.68,26.67) v1(106.68,24.13) v1(106.68,21.59) v1(106.68,19.05) v1(106.68,16.51) v1(106.68,12.7) v1(106.68,10.16) v1(106.68,5.59) v1(106.68,3.81) v2(50.8,7.75) v2(50.8,6.73) v2(51.69,7.75) v2(51.69,6.73) v2(52.58,7.75) v2(52.58,6.73) v2(71.88,13.33) v2(71.88,12.57) v2(71.88,11.81) v2(71.88,11.05) v2(71.88,10.29) v2(73.03,13.33) v2(73.03,10.29) v2(74.17,13.33) v2(74.17,11.81) v2(74.17,11.05) v2(74.17,10.29)
PGND: length 20.5
  TOP w0.508: 37.2,4.8 P1.2 ; P1.2 38.92,4.8 ; P1.2 37.2,3.08 ; P1.2 38.92,3.08 ; 51.94,45.57 51.94,46.86 ; 51.94,46.86 49.78,46.86 ; 51.94,46.86 51.94,48.16 ; C24.2 36.2,37.34 v1(37.34,37.34)
  L2_GND w0.508: 37.2,3.08 P1.2 ; P1.2 38.92,4.8 ; P1.2 37.2,4.8 ; P1.2 38.92,3.08
  BOTTOM w0.508: P1.2 38.92,4.8 ; P1.2 37.2,3.08 ; P1.2 38.92,3.08 ; P1.2 37.2,4.8
  vias: v1(35.43,18.41) v1(35.43,17.14) v1(35.43,15.88) v1(35.43,14.6) v1(35.43,13.21) v1(35.43,11.81) v1(35.43,10.29) v1(35.43,8.76) v1(35.43,7.24) v1(35.43,5.71) v1(35.43,4.19) v1(35.43,2.79) v1(35.56,1.4) v1(37.21,1.4) v1(38.61,1.4) v1(40.01,1.4) v1(42.16,24.89) v1(42.16,23.49) v1(42.16,22.1) v1(42.16,20.45) v1(42.16,19.05) v1(42.16,17.4) v1(42.16,16) v1(42.16,14.35) v1(42.16,12.95) v1(42.16,11.3) v1(42.16,9.91) v1(42.16,8.51) v1(42.16,7.11) v1(42.16,5.71) v1(43.43,10.41) v1(43.56,4.57) v1(44.96,1.4) v1(47.75,44.7) v1(47.75,42.42) v1(47.75,40.13) v1(47.75,37.46) v1(47.88,52.2) v1(47.88,50.55) v1(47.88,48.77) v1(47.88,46.61) v1(49.91,52.07)
VCC: length 19.3
  TOP w0.381: v1(53.47,24.89) 53.47,25.53 53.97,26.03 C4.1 53.97,26.54 53.63,26.87 U3.1 ; v1(45.72,23.37) C11.1
  TOP w0.508: C29.1 C11.1 ; C29.1 46.87,25.49 46.86,25.5 U1.6 ; C29.1 v1(45.72,24.64) ; JP3.2 TP8.1
  TOP w0.635: TP8.1 v1(87.25,12.83) ; v1(85.47,5.89) 81.23,5.89 80.78,5.45 R23.1
VIN: length 15.8
  TOP w0.254: U5.1 52.44,9.01 53.17,9.74 53.17,10.03
  TOP w0.508: R13.1 v1(60.58,13.72)
  TOP w0.635: TP10.1 v1(55.5,18.41) ; 60.33,7.98 61.37,7.98 v1(61.72,7.62) ; v1(61.72,9.78) 61.21,9.27 Q2.8 ; v1(53.17,13.02) R17.2 R14.1 53.17,10.03 ; E2.2 v1(45.34,10.49)
  TOP w0.762: D1.1 45.22,15.61 46.36,14.48 v1(46.36,13.33)
AD8210_OUTPUT: length 51
  TOP w0.254: v1(60.58,26.54) R5.1
  TOP w0.381: C30.1 49.02,20.32 TP1.1 ; C30.1 47.2,20.35 R29.2 ; C30.1 47.24,19.18 v1(47.24,19.18) ; U7.2 v1(75.06,34.54)
  BOTTOM w0.254: v1(47.24,19.18) 48.9,20.83 58.04,20.83 60.58,23.37 v1(60.58,26.54) 58.55,28.57 58.55,31.75 59.18,32.38 64.07,32.38 66.29,34.61 66.29,34.79 67,35.49 67.63,35.49 68.58,34.54 v1(75.06,34.54)
AIN_ARD: length 65.7
  TOP w0.254: v1(59.44,29.97) 58.8,29.97 58.5,29.67 JP2.1
  TOP w0.305: v1(88.9,7.62) 88.14,6.86 P10.2 P11.2 P12.2 P13.2 P14.2 P15.2
  TOP w0.381: P15.2 100.97,7.37 TP14.1
  BOTTOM w0.254: v1(59.44,29.97) 69.34,29.97 71.25,28.07 77.23,28.07 82.56,22.73 87,22.73 88.9,20.83 v1(88.9,7.62)
AREF_ARD: length 49
  TOP w0.254: P6.8 63.88,48.89 TP16.1 ; P9.2 v1(58.55,23.62)
  BOTTOM w0.254: P6.8 60.71,49.53 57.02,49.53 56.13,48.64 56.13,47.64 55.61,47.12 54.99,47.12 53.72,45.85 53.72,40.85 49.53,36.66 49.53,31.24 52.96,27.81 52.96,26.16 52.58,25.78 52.58,24.52 53.48,23.62 v1(58.55,23.62)
FAULT_DETECT: length 17.4
  TOP w0.254: v1(79.38,30.1) 79.88,30.61 P24.2 ; TP17.1 v1(71.88,28.96)
  TOP w0.381: U7.8 71.83,32.31 71.88,32.26 TP17.1 70.48,30.86 70.26,31.09 P22.1
  BOTTOM w0.254: v1(79.38,30.1) 73.03,30.1 v1(71.88,28.96)
FAULT_DETECT_ARD: length 20.4
  TOP w0.254: P7.3 96.52,37.46 95.02,35.97 P31.1
FET_DRIVER_OUTPUT: length 12.2
  TOP w0.508: 51.59,39.5 R4.1 ; R4.1 52.24,38.75 ; R4.1 52.24,40.25 ; 49.1,39.8 TP2.1 ; TP2.1 49.1,37.92 ; TP2.1 50.98,39.8 ; TP2.1 50.98,37.92
  TOP w0.762: Q1.1 51.94,43.08 ; Q1.1 51.94,40.49 ; Q1.1 49.78,41.78
IOREF: length 138.4
  TOP w0.254: 91.53,26.28 90.55,27.26 U4.1 ; 91.53,26.28 C27.1 C28.2 v1(95.24,26.28) ; 91.53,26.28 91.31,26.06 P36.1 ; v1(65.53,29.08) 65.53,30.99 64.26,32.26 TP12.1 62.99,33.59 62.89,33.69 P26.1 64.77,35.43 v1(65.02,35.69) ; v1(55.24,33.66) 55.25,33.65 C6.1 55.25,32.22 55.59,31.89 U3.5
  BOTTOM w0.254: P5.2 69.84,3.8 84.34,3.8 84.56,3.58 85.84,3.58 86.36,4.1 86.36,10.68 88.14,12.46 88.14,20.83 86.74,22.22 82.35,22.22 77.02,27.56 70.99,27.56 69.47,29.08 v1(65.53,29.08) ; v1(55.24,33.66) 63.73,33.66 65.02,34.95 v1(65.02,35.69) 67.31,37.97 78.11,37.97 81.91,34.16 81.91,28.58 85.22,25.27 85.98,25.27 88.52,22.73 94.11,22.73 95.24,23.87 v1(95.24,26.28)
LOGICTRANSLATOROUTPUT: length 33.8
  TOP w0.254: P19.2 v1(79.38,27.94) ; v1(59.68,31.5) 60.96,31.5 TP3.1
  TOP w0.381: v1(59.68,31.5) R7.2
  BOTTOM w0.254: v1(59.68,31.5) 66.04,31.5 67.06,32.51 78.61,32.51 80.26,30.86 80.26,28.83 v1(79.38,27.94)
LT1671_QN_OUT: length 45.1
  TOP w0.254: P32.1 v1(89.53,21.72)
  TOP w0.381: P28.1 65.53,38.1 66.17,37.46 66.17,34.54 65.66,34.04 65.66,33.02 65.79,32.89 v1(65.79,32.84) ; P21.2 P22.2
  TOP w0.508: v1(65.79,32.84) 66.13,32.84 66.27,32.98 66.38,32.98 66.67,33.27 R25.1 67.3,33.27 67.54,33.5 P21.2
  BOTTOM w0.254: v1(65.79,32.84) 66.22,33.27 79.04,33.27 80.9,31.41 80.9,28.83 84.96,24.76 85.68,24.76 88.73,21.72 v1(89.53,21.72)
LT3433_EN: length 2.7
  TOP w0.254: JP7.3 64.34,10.36 64.41,10.29 R22.1
LT4367_FAULT_ARD: length 42
  TOP w0.254: P29.1 95.63,30.86 100.32,35.55 100.32,51.32 99.06,52.58 85.6,52.58 P7.8
LTC2312_CONV: length 44
  TOP w0.254: v1(51.5,33.35) 51.05,32.91 51.05,31.5 51.91,30.64 U3.8 ; P2.1 P2.3 P2.5
  BOTTOM w0.254: v1(51.5,33.35) 52.18,34.04 54.1,35.95 54.1,38.78 55.24,39.92 55.24,42.46 55.58,42.8 62.74,42.8 63.88,41.66 66.81,41.66 71.64,46.48 72.64,46.48 P2.1
LTC2312_VREF: length 48.3
  TOP w0.305: R9.2 v1(81.03,33.69)
  TOP w0.381: U3.2 54.28,27.22 55,26.51 C7.1
  TOP w0.508: P9.1 54.97,20.98 ; P9.1 54.97,24.64 54.87,24.74 54.87,25.04 v1(54.81,25.11) 55,25.3 C7.1 ; P9.1 JP1.1
  TOP w0.635: 54.97,20.98 TP6.1
  BOTTOM w0.254: v1(81.03,33.69) 79.03,35.69 75.06,35.69 74.04,36.7 67.49,36.7 63.81,33.02 56.64,33.02 56.39,32.77 56.39,31.76 56.64,31.51 56.64,28.57 54.81,26.74 v1(54.81,25.11)
LTC4367_FAULT: length 81.1
  TOP w0.254: v1(65.53,7.95) 64.9,7.95 64.16,8.69 JP7.1 ; P20.2 v1(86.87,20.83) ; JP6.1 48.97,3.63 50.51,5.17 51.12,5.17 51.44,5.49 U5.6
  TOP w0.305: TP18.1 48.51,5.59 v2(48.51,4.7) JP6.1
  BOTTOM w0.381: v2(48.51,4.7) 48.01,5.21 48.01,13.08 49.53,14.6 57.91,14.6 59.88,12.64 63.75,12.64 63.99,12.88 67.06,12.88 68.01,11.94 68.01,11.15 67.03,10.17 65.14,10.17 64.58,9.61 64.58,8.82 65.45,7.95 v1(65.53,7.95) 65.54,7.94 67.58,7.94 68.12,7.39 76.02,7.39 76.82,8.19 78.82,8.19 86.87,16.24 v1(86.87,20.83)
LTC4441_DRVCC: length 31.8
  TOP w0.508: U2.7 57.28,44.33 57.02,44.58 55.75,44.58 55.56,44.77 v1(55.24,44.77) ; R11.2 v1(64.26,43.69) ; v1(57.02,48.01) 57.79,47.24 JP4.1
  BOTTOM w0.635: v1(55.24,44.77) 55.44,44.96 55.69,44.96 57.02,46.29 v1(57.02,48.01) 57.84,48.82 66.88,48.82 68.01,47.69 68.01,45.28 67.63,44.89 67.63,44.89 67,44.26 64.83,44.26 v1(64.26,43.69)
LTC4441_FB: length 7.6
  TOP w0.508: 59.82,41.58 61.07,41.58 61.98,42.49 R10.1 R11.1 61.98,45.2 61.16,46.02 JP4.3
MISO_ARD: length 79.7
  TOP w0.254: R12.2 v1(53.22,33.53) ; P17.1 v1(69.09,45.34)
  BOTTOM w0.254: v1(53.22,33.53) 52.08,32.38 51.2,32.38 50.55,33.04 50.55,35.94 54.74,40.13 54.74,42.67 55.37,43.31 63.39,43.31 63.89,42.8 64.63,42.8 65.39,43.56 67.31,43.56 v1(69.09,45.34) 72.01,48.26 77.85,48.26 78.74,47.37 78.74,43.69 79.49,42.94 84.57,42.94 87,40.51 95.12,40.51 98.04,37.59 98.04,32.26 99.82,30.48 P3.1
MOSI_ARD: length 45
  TOP w0.254: P16.1 v1(71.75,45.34)
  BOTTOM w0.254: P3.4 102.88,29.2 99.96,29.2 97.41,31.75 97.41,36.07 95.12,38.35 88.14,38.35 84.07,42.42 77.09,42.42 76.33,41.66 74.17,41.66 71.75,44.07 v1(71.75,45.34)
OC_RESET: length 29.8
  TOP w0.254: P23.2 v1(87.12,37.97) ; C25.2 v1(77.47,41.53) ; P27.1 v1(65.66,40.64)
  BOTTOM w0.254: v1(87.12,37.97) 85.09,40 78.99,40 v1(77.47,41.53) 76.07,40.13 66.17,40.13 v1(65.66,40.64)
OC_RESET_ARD: length 27.5
  TOP w0.254: P30.1 95,33.4 97.79,36.19 97.79,51.31 97.04,52.06 92.7,52.06 P7.5
PWM_SIG: length 48.2
  TOP w0.254: P34.1 P34.3 P34.5 ; TP15.1 v2(94.55,28.32) P25.1
  BOTTOM w0.254: P34.5 88.9,42.93 90.3,41.53 94.87,41.53 99.19,37.21 99.19,33.4 100.46,32.13 104.65,32.13 105.66,31.11 105.66,27.56 104.79,26.68 96.19,26.68 v2(94.55,28.32)
RSENSE_N: length 37.2
  TOP w0.508: R28.1 36.82,34.3 ; R28.1 36.2,33.73 ; R28.1 35.57,34.3
  TOP w0.635: TP5.1 41.16,31.76 R3.1 39.87,30.23
  TOP w1.27: R1.2 39.6,31.79 ; R1.2 37.59,33.57 ; R1.2 35.58,31.79 ; 39.97,34.19 D2.A ; D2.A 39.97,37.69 ; D2.A 38.71,35.94 ; 40.51,38.35 Q1.4 ; Q1.4 35.81,44.32 ; Q1.4 45.21,44.32 ; Q1.4 40.51,50.29
RSENSE_P: length 14.1
  TOP w0.635: TP4.1 41.16,27.17 R2.1 39.88,28.83
  TOP w0.762: 37.2,15.4 P8.2 ; P8.2 37.2,17.12 ; P8.2 38.92,17.12 ; P8.2 38.92,15.4
  TOP w1.27: R1.1 39.6,27.14 ; R1.1 35.58,27.14 ; R1.1 37.59,25.36
SCLK_ARD: length 96.9
  TOP w0.254: v1(53.85,29.34) 54.28,29.77 U3.7 ; v1(66.55,45.34) P18.1
  BOTTOM w0.254: v1(66.55,45.34) 66.17,45.72 57.77,45.72 55.87,43.81 55.16,43.81 54.23,42.88 54.23,40.64 50.04,36.45 50.04,31.45 52.15,29.34 v1(53.85,29.34) 54.36,29.84 54.36,34.02 54.88,34.54 55.63,34.54 55.88,34.29 63.64,34.29 64.14,34.78 64.14,36.44 66.31,38.61 84.71,38.61 86.23,37.08 95.5,37.08 96.65,35.94 96.65,31.24 99.95,27.94 P3.3
SHDN_N_LTC4367: length 10.7
  TOP w0.254: v1(49.75,5.84) 49.76,5.85 U5.5
  TOP w0.381: v1(51.47,13.02) R17.1
  BOTTOM w0.254: v1(51.47,13.02) 49.28,10.82 49.28,6.32 v1(49.75,5.84)
SW_H_LT3433: length 24.8
  TOP w0.381: U6.3 69.09,12.79 68.45,13.42 68.45,15.14 68.97,15.66 C16.2
  TOP w0.508: D5.C 66.29,20.88 ; D5.C 66.29,19.1 ; D5.C 64.99,19.99 ; D5.C 67.81,19.99 68.97,18.83 C16.2 ; L1.2 70.7,26.89 ; L1.2 70.7,19.09 ; L1.2 69.13,22.99 ; L1.2 72.28,22.99
UNNAMED_4_AD8210_I5_INV: length 8.6
  TOP w0.254: U1.1 49.4,31.34 48.15,30.09 C1.2 42.29,30.09 R3.2
UNNAMED_4_AD8210_I5_NINV: length 8.7
  TOP w0.254: R2.2 42.42,29.09 C1.1 48.15,29.09 49.4,27.84 U1.8
UNNAMED_4_AD8210_I5_OUT: length 6
  TOP w0.508: 45.59,27.05 45.59,25.95 44.7,25.06 44.7,22.62 45.51,21.82 R29.1
UNNAMED_4_AD8210_I5_VREF1: length 5.8
  TOP w0.254: JP1.2 50.93,24.89 50.42,25.4 48.36,25.4 48.13,25.63 U1.7
UNNAMED_4_ADG3304_I147_A1: length 2.6
  TOP w0.254: U4.2 91.77,28.8 92.25,28.32 P25.2
UNNAMED_4_ADG3304_I147_A2: length 3.2
  TOP w0.254: U4.3 92,29.45 92.94,30.39 P29.2
UNNAMED_4_ADG3304_I147_A3: length 4.9
  TOP w0.254: P30.2 92.94,32.93 92.08,32.07 92.08,30.63 91.54,30.1 U4.4
UNNAMED_4_ADG3304_I147_A4: length 6.7
  TOP w0.254: P31.2 89.57,35.15 88.77,34.35 88.77,31.24 89.27,30.75 U4.5
UNNAMED_4_ADG3304_I147_EN: length 29.5
  TOP w0.254: U4.8 84.71,32.71 85.08,33.08 R6.1 v1(85.08,36.44) ; v1(91.16,23.77) P32.2 P36.2
  BOTTOM w0.254: v1(91.16,23.77) 93.73,26.34 93.73,35.56 92.84,36.44 v1(85.08,36.44)
UNNAMED_4_ADG3304_I147_Y1: length 2.9
  TOP w0.254: U4.13 83.49,28.8 82.63,27.94 P19.1
UNNAMED_4_ADG3304_I147_Y2: length 5
  TOP w0.254: U4.12 85.99,29.45 86.87,28.57 P20.1
UNNAMED_4_ADG3304_I147_Y3: length 7
  TOP w0.254: P23.1 87.12,30.86 86.36,30.1 U4.11
UNNAMED_4_ADG3304_I147_Y4: length 2.6
  TOP w0.254: U4.10 82.97,30.75 82.83,30.61 P24.1
UNNAMED_4_CAP_I113_N1: length 1
  TOP w0.635: C24.1 R28.2
UNNAMED_4_CAP_I138_N1: length 5.3
  TOP w0.381: Q3.1 73.58,40.08 74.26,39.41 R24.1 75.98,39.25 C25.1
UNNAMED_4_CAP_I190_N1: length 3
  TOP w0.254: JP2.2 59.3,28.83 C2.1 R5.2
UNNAMED_4_CN2P_I185_N1: length 11.2
  TOP w0.762: F2.1 45.8,5.06 v1(46.29,4.57) F1.2
  TOP w1.27: D2.C v1(47.24,35.94)
  L3_PWR w0.508: P1.1 38.92,9.88 ; P1.1 37.2,9.88 ; P1.1 38.92,8.16 ; P1.1 37.2,8.16
UNNAMED_4_CN2P_I186_N1: length 24.6
  TOP w1.016: F1.1 43.62,2.22 43.05,1.65 41.62,1.65 40.39,2.88 40.39,20.32 39.37,21.34 P8.1
UNNAMED_4_DIOLED_I105_N: length 1.7
  TOP w0.381: DS5.C 68,36.07 67.5,36.57 R26.2
UNNAMED_4_DIOLED_I105_P: length 7.8
  TOP w0.381: U7.7 70.48,34.54 70.26,34.32 P21.1 69.09,35.01 69.54,35.47 DS5.A 69.54,36.5 69.22,36.83 68.24,36.83 67.82,37.25 JP8.1
UNNAMED_4_FERRITE_I59_N1: length 2.6
  TOP w0.635: 43.56,8.76 43.48,8.68 43.48,6.35 F2.2
UNNAMED_4_LINLT1671_I98_: length 4.6
  TOP w0.381: R8.1 R9.1 78.65,35.39 78.23,35.81 U7.3
UNNAMED_4_LINLT1671_I98_LATCHEN: length 5.1
  TOP w0.381: R27.2 70.48,37.6 71,37.08 U7.5 72.26,37.08 72.64,37.46 Q3.3
UNNAMED_4_LINLTC4441_I24_IN: length 2.3
  TOP w0.381: R7.1 58.68,34.92 58.55,35.06 U2.3
UNNAMED_4_LINLTC4441_I24_OUT: length 3.3
  TOP w0.381: R4.2 54.61,39.5 56.01,40.89 U2.8
UNNAMED_4_LINLTC231214_I50_AIN: length 2.1
  TOP w0.254: JP2.3 56.57,27.99 56.52,28.04 U3.4
UNNAMED_4_LINLTC231214_I50_SDO: length 2
  TOP w0.254: U3.6 54.94,31.54 54.22,32.26 R12.1
UNNAMED_4_NC2P_I121_N2: length 7.9
  TOP w0.508: 59.82,36.4 60.35,36.4 61.32,35.43 P26.2 P28.2 P27.2
UNNAMED_4_NC3PJMPR_I135_COM: length 1.8
  TOP w0.381: JP8.2 69.59,38.61 R27.1
UNNAMED_5_CN6P_I88_N1: length 2.7
  TOP w0.305: P10.1 88.14,4.45 88.9,3.68 P4.1
UNNAMED_5_CN6P_I88_N2: length 2.7
  TOP w0.305: P11.1 90.68,4.45 91.44,3.68 P4.2
UNNAMED_5_CN6P_I88_N3: length 2.7
  TOP w0.305: P12.1 93.22,4.45 93.98,3.68 P4.3
UNNAMED_5_CN6P_I88_N4: length 2.7
  TOP w0.305: P13.1 95.76,4.32 96.52,3.56 P4.4
UNNAMED_5_CN6P_I88_N5: length 2.7
  TOP w0.305: P4.5 99.06,3.68 98.43,4.32 P14.1
UNNAMED_5_CN6P_I88_N6: length 2.7
  TOP w0.305: P15.1 101.6,4.29 P4.6
UNNAMED_5_CN6PODDEVEN_I95_N2: length 5.1
  TOP w0.305: P34.2 83.82,48.26 P7.7
UNNAMED_5_CN6PODDEVEN_I95_N4: length 5.1
  BOTTOM w0.254: P34.4 86.36,48.26 P7.6
UNNAMED_5_CN6PODDEVEN_I95_N6: length 7.6
  BOTTOM w0.305: P34.6 91.06,48.89 93.47,48.89 93.98,49.4 P7.4
UNNAMED_5_CN10P_I91_N1: length 4.2
  BOTTOM w0.305: P6.1 80.01,50.55 P2.6
UNNAMED_5_CN10P_I91_N2: length 4.2
  TOP w0.254: P2.4 77.47,48.64 77.22,48.89 P6.2
UNNAMED_5_CN10P_I91_N3: length 4.2
  TOP w0.305: P6.3 74.68,49.02 74.93,48.77 P2.2
UNNAMED_5_CN10P_I91_N4: length 3.3
  TOP w0.254: P16.2 71.75,49.26 72.14,49.64 P6.4
UNNAMED_5_CN10P_I91_N5: length 3.4
  TOP w0.254: P17.2 69.09,49.14 69.6,49.64 P6.5
UNNAMED_5_CN10P_I91_N6: length 3.4
  TOP w0.254: P6.6 67.06,49.64 66.55,49.14 P18.2
UNNAMED_6_CAP_I20_N1: length 10.4
  TOP w0.254: U6.12 78.05,11.49
  TOP w0.381: D8.C 82.04,7.72 82.81,8.5 82.81,9.31 81.97,10.15 C19.1 80.26,10.53 79.88,10.91 78.63,10.91 78.05,11.49
UNNAMED_6_CAP_I25_N1: length 5.8
  TOP w0.381: U6.2 69.41,13.44 69.09,13.76 69.09,14.48 69.98,15.37 69.98,16.38 C16.1
  TOP w0.508: C16.1 D6.C
UNNAMED_6_CAP_I27_N1: length 4.1
  TOP w0.381: U6.10 75.85,10.17 76.65,10.17 76.91,9.91 76.91,9.7 77.33,9.29 78,9.29 78.87,10.15 C18.1
UNNAMED_6_CAP_I32_N1: length 1.2
  TOP w0.508: R19.2 67.32,9.4 C17.1
UNNAMED_6_CAP_I34_N1: length 3.2
  TOP w0.381: U6.6 68.74,10.84 R19.1 68.32,9.25 C15.1
UNNAMED_6_DIO_I54_N: length 14.6
  TOP w0.254: D3.C v1(62.36,11.68)
  TOP w0.508: DS2.A DS1.A 60.89,3.5 v1(60.2,4.19)
  BOTTOM w0.381: v1(62.36,11.68) 61.09,11.68 59.69,10.29 59.69,4.57 60.07,4.19 v1(60.2,4.19)
UNNAMED_6_DIO_I54_P: length 2.1
  TOP w0.381: R13.2 58.3,12.64 58.45,12.5 D3.A
UNNAMED_6_DIOLED_I52_N: length 38.8
  TOP w0.254: JP6.2 v2(47.37,2.79)
  TOP w0.381: v1(63.75,1.4) 63.25,1.9 DS2.C
  BOTTOM w0.254: v2(47.37,2.79) 47.54,2.79 49.21,4.46 49.21,4.99 48.77,5.43 48.77,12.95 49.78,13.97 53.48,13.97 54.23,13.21 54.23,7.05 59.86,1.42 60.24,1.42 61.22,2.41 62.11,2.41 63.12,1.4 v1(63.75,1.4)
UNNAMED_6_DIOLED_I60_P: length 1.5
  TOP w0.254: R18.2 77.55,4.78 77.73,4.95 DS3.A
UNNAMED_6_DIOLED_I63_P: length 1.6
  TOP w0.254: R23.2 DS4.A
UNNAMED_6_DIOSCHOTTKY_I22_P: length 31.6
  TOP w0.381: v1(76.45,15.24) 77.09,14.6 77.09,13.89 76.64,13.44 U6.15
  TOP w0.508: D7.A 79.25,22.06 ; D7.A 77.98,20.79 ; D7.A v1(83.1,20.79) ; D7.A 79.25,19.52 ; L1.1 76.92,22.99 ; L1.1 73.77,22.99 ; L1.1 75.35,26.89 ; L1.1 75.35,19.09
  BOTTOM w1.27: v1(76.45,15.24) 79.25,15.24 83.1,19.09 v1(83.1,20.79)
UNNAMED_6_DIOZNR_I46_N: length 13
  TOP w0.254: Q2.2 55.63,8 ; 55.63,8 55.88,8.25 55.88,11.11 56.29,11.52 C10.2 56.29,13.45 D4.C ; 55.63,8 55.88,7.75 55.88,5.71 55.63,5.46 Q2.4 54.1,5.46 53.72,5.85 U5.8
UNNAMED_6_DIOZNR_I46_P: length 8.7
  TOP w0.254: Q2.3 54.53,6.73 53.85,7.42 53.85,9.02 54.1,9.27 Q2.1 54.86,11.26 C10.1 55.29,13.63 D4.A
UNNAMED_6_LINLT3433_I2_BURSTEN: length 16
  TOP w0.381: JP5.2 64.9,5.97 v1(65.53,6.6) ; U6.5 68.02,11.49 67.96,11.54 v1(67.06,11.54)
  BOTTOM w0.381: v1(65.53,6.6) 64.63,6.6 63.63,7.61 63.63,11.62 64.26,12.25 66.35,12.25 v1(67.06,11.54)
UNNAMED_6_LINLT3433_I2_SHDNN: length 18.2
  TOP w0.254: v1(65.53,9.22) 64.69,9.22 64.38,9.52 JP7.2
  TOP w0.381: U6.11 77.1,10.84 77.56,10.38 v1(77.75,10.38)
  BOTTOM w0.381: v1(65.53,9.22) 67.2,9.22 68.16,8.25 75.99,8.25 77.75,10.01 v1(77.75,10.38)
UNNAMED_6_LINLT3433_I2_VFB: length 8.2
  TOP w0.381: R20.1 71.97,8.37 71.7,8.64 69.6,8.64 69.1,9.13 69.1,9.88 69.41,10.19 U6.7
  TOP w0.762: R20.1 R21.1
UNNAMED_6_LINLTC4367_I1_OV: length 5.6
  TOP w0.254: U5.3 51.44,9.14 51.18,9.4 50.93,9.4
  TOP w0.381: 50.93,9.4 49.21,9.4 48.43,10.19 R15.2 R16.1
UNNAMED_6_LINLTC4367_I1_UV: length 3.2
  TOP w0.254: U5.2 51.94,9.52
  TOP w0.381: R15.1 R14.2 51.94,9.82 51.94,9.52
VOUT_LT3433: length 32
  TOP w0.381: 84.71,27.26 U4.14 ; 77.02,12.14 U6.13 ; C23.1 77.21,32.35 77.01,32.54 U7.1
  TOP w0.508: JP3.1 83.82,13.67 ; JP3.1 82.8,14.22 ; JP3.1 81.79,13.67 ; C22.1 80.68,13.91 ; C22.1 78.57,13.91 ; C22.1 79.63,14.81 ; 77.58,12.14 77.02,12.14 ; D7.C 79.25,18.07 ; D7.C 79.25,15.53 ; D7.C 77.98,16.8 ; D7.C 80.52,16.8 ; TP9.1 83.49,17.7 ; TP9.1 81.61,15.82 ; TP9.1 81.61,17.7 ; TP9.1 83.49,15.82 ; 75.55,16.38 D6.A 74.8,17.49 ; v1(84.83,23.88) C9.2 C8.1 84.83,27.14 84.71,27.26
  TOP w0.635: D8.A 77.34,7.37 v1(77.22,7.24) ; v1(77.21,29.08) 78.03,29.9 78.03,30.8 C23.1
  TOP w0.762: v1(77.22,7.24) 76.96,7.49 R21.2
  vias: v1(81.15,14.58)
VOUT_LTC4367: length 49.5
  TOP w0.254: U5.7 51.94,5.49 52.25,5.17 53.5,5.17 54.27,4.4 v1(55.63,4.4) ; JP6.3 v2(47.37,1.96)
  TOP w0.381: U6.4 68.2,12.14 67.31,13.03 67.31,13.06 ; JP5.1 62.26,6.81 62.12,6.67 60.41,6.67 60.33,6.76
  TOP w0.508: v1(55.63,4.4) 55.63,2.79 C12.1 ; 67.31,13.06 67.31,13.13 ; U2.6 58.55,43.3 C5.1 C26.1 58.81,45.36 59.29,45.85 59.88,45.85 60.33,46.3 JP4.2 ; v1(61.59,4.95) 61.09,5.46 60.33,5.46 60.33,6.76
  TOP w0.635: v1(60.33,39.24) 59.18,39.24 58.55,39.88 U2.6 ; v1(64.65,11.3) R22.2 65.91,12.13 66.4,12.62 66.8,12.62 67.31,13.13 C14.1 67.31,15.5 TP13.1 TP7.1
  BOTTOM w0.254: v1(55.63,4.4) 54.77,5.26 50.94,5.26 47.64,1.96 v2(47.37,1.96)

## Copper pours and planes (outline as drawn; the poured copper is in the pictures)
AGND on TOP: outline of 141 points within 43.69,0.89 107.19,52.7 ; 30 cut-outs
AGND on BOTTOM: 49.15,0.89 49.15,5.87 45.47,5.87 45.47,11.68 43.69,11.68 43.69,35.05 53.47,35.05 53.47,41.4 54.74,41.4 54.74,50.29 52.83,50.29 52.83,52.7 105.28,52.7 105.28,50.67 107.19,50.67 107.19,2.92 104.78,2.92 104.78,0.89 ; 23 cut-outs
